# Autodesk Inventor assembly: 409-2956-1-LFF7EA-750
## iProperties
Created: 2010-06
Part Number: 409-2956-1-LFF7EA-750
Document SubType Name: Weldment
Designer: S. Boerckel
Mass: 7288.2 g
Surface Area: 2849.18 cm^2
Volume: 927.7 cm^3
Density: 7.8562 g/cm^3
Description: RECERCULATION SPOOL
Weld Material: Welded Steel Mild
Material: WEDLMENT
Author: S. Boerckel
Revision Number: B
Subject: DEMIN WATER FORWARDING PUMP SKID-7EA
